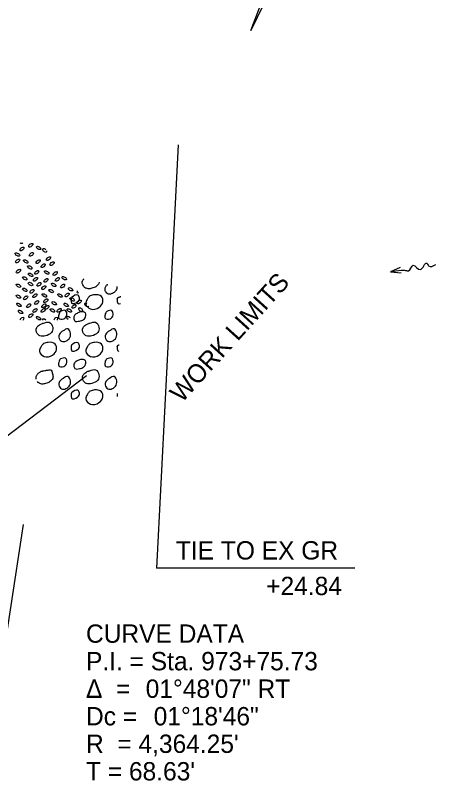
# Model space of a CAD drawing. Extents: x 1785 to 2465, y -264 to 295.
# Drawn here: x 2238.8 to 2303, y -70.4 to 46.4 of the extents above; entities that cross this region are included whole.
import ezdxf

# ---------------------------------------------------------------- set-up
doc = ezdxf.new("R2010")
doc.units = 0
for name, color, linetype in [('DR_P_Culvert', 7, 'Continuous'), ('DR_X_Erosion_Control', 7, 'Continuous'), ('MT_P_Lane_Line', 7, 'Continuous'), ('PV_P_Shoulder', 7, 'Continuous'), ('RW_X_CL_100_Curve_Data', 7, 'Continuous'), ('TX_P_1', 7, 'Continuous')]:
    doc.layers.add(name, color=color, linetype=linetype)

msp = doc.modelspace()

# ---------------------------------------------------------------- linework, layer by layer
at = {"layer": 'DR_P_Culvert'}
msp.add_line((2235.1, -63.51), (2240.05, -31.26), dxfattribs=at)
at = {"layer": 'DR_X_Erosion_Control'}
for centre, major_axis, start_param, end_param in [((2239.61, 11.87), (0.33, -0.195), 4.705104, 6.283185), ((2239.61, 11.87), (0.33, -0.195), 0, 0.101744), ((2243.28, 10.54), (0.33, -0.195), 1.269797, 6.283185), ((2243.28, 10.54), (0.33, -0.195), 0, 0.516671), ((2248.52, 4.35), (0.296, 0.243), 2.064503, 4.182694), ((2249.71, 2.22), (0.33, -0.195), 1.720823, 6.283185), ((2248.76, 1.5), (0.33, -0.195), 0, 5.743204), ((2248.76, 1.5), (0.33, -0.195), 6.256482, 6.283185), ((2249.71, 2.22), (0.33, -0.195), 0, 0.065645), ((2239.81, 0.03), (0.296, 0.243), 0, 2.52413), ((2239.81, 0.03), (0.296, 0.243), 4.857893, 6.283185), ((2243.28, -0.19), (0.33, -0.195), 1.299888, 3.572242), ((2244.98, 0.03), (0.296, 0.243), 0, 2.52413), ((2244.98, 0.03), (0.296, 0.243), 4.857893, 6.283185), ((2246.95, 0.2), (0.33, -0.195), 1.011335, 4.705166)]:
    msp.add_ellipse(centre, major_axis=major_axis, ratio=0.503326, start_param=start_param, end_param=end_param, dxfattribs=at)
for centre, major_axis in [((2239.81, 10.76), (0.296, 0.243)), ((2241.16, 11.33), (0.296, 0.243)), ((2242.36, 10.91), (0.33, -0.195)), ((2239.12, 9.91), (0.33, -0.195)), ((2241.24, 9.92), (0.296, 0.243)), ((2243.87, 9.29), (0.296, 0.243)), ((2239.16, 8.94), (0.296, 0.243)), ((2240.4, 8.85), (0.33, -0.195)), ((2241, 7.94), (0.33, -0.195)), ((2242.29, 8.83), (0.296, 0.243)), ((2243.05, 8.2), (0.296, 0.243)), ((2244.41, 8.52), (0.296, 0.243)), ((2239.27, 7.37), (0.296, 0.243)), ((2241.12, 6.82), (0.33, -0.195)), ((2242.06, 7.18), (0.296, 0.243)), ((2243.6, 7.16), (0.33, -0.195)), ((2244.89, 7.01), (0.296, 0.243)), ((2240.25, 6.27), (0.33, -0.195)), ((2241.88, 6.14), (0.296, 0.243)), ((2243.49, 5.97), (0.296, 0.243)), ((2245.22, 6.1), (0.296, 0.243)), ((2246.26, 6.3), (0.33, -0.195)), ((2239.28, 5.15), (0.33, -0.195)), ((2240.25, 4.53), (0.33, -0.195)), ((2241.12, 5.41), (0.33, -0.195)), ((2242.41, 5.35), (0.296, 0.243)), ((2243.15, 4.86), (0.296, 0.243)), ((2244.67, 5.27), (0.33, -0.195)), ((2246.02, 5.1), (0.296, 0.243)), ((2247.24, 4.6), (0.33, -0.195)), ((2239.28, 3.48), (0.33, -0.195)), ((2240.37, 3.3), (0.296, 0.243)), ((2241.35, 4.31), (0.296, 0.243)), ((2241.79, 3.63), (0.296, 0.243)), ((2243.23, 3.66), (0.33, -0.195)), ((2244.26, 4.34), (0.33, -0.195)), ((2245.64, 3.65), (0.33, -0.195)), ((2246.71, 3.74), (0.296, 0.243)), ((2239.36, 2.22), (0.33, -0.195)), ((2240.83, 2.09), (0.296, 0.243)), ((2242.06, 2.59), (0.296, 0.243)), ((2243.16, 2.09), (0.296, 0.243)), ((2243.45, 2.85), (0.296, 0.243)), ((2244.75, 2.47), (0.33, -0.195)), ((2246.57, 2.22), (0.33, -0.195)), ((2247.47, 3.06), (0.33, -0.195)), ((2248.55, 2.68), (0.296, 0.243)), ((2239.61, 1.15), (0.33, -0.195)), ((2241.8, 1.37), (0.296, 0.243)), ((2243.05, 1.38), (0.296, 0.243)), ((2243.64, 1.86), (0.296, 0.243)), ((2244.46, 1.38), (0.33, -0.195)), ((2245.48, 1.38), (0.296, 0.243)), ((2247.03, 1.38), (0.33, -0.195)), ((2247.76, 1.99), (0.296, 0.243)), ((2241.16, 0.6), (0.296, 0.243)), ((2242.36, 0.19), (0.33, -0.195))]:
    msp.add_ellipse(centre, major_axis=major_axis, ratio=0.503326, dxfattribs=at)
at = {"layer": 'MT_P_Lane_Line'}
for p, q in [((2297.57, 7.94), (2296.06, 7.26)), ((2296.06, 7.26), (2297.71, 7.09))]:
    msp.add_line(p, q, dxfattribs=at)
msp.add_spline([(2296.06, 7.26), (2297.7, 7.52), (2298.38, 7.48), (2298.81, 7.4), (2299.53, 8.26), (2300.62, 7.6), (2301.6, 8.59), (2301.89, 8.19), (2302.97, 8.37)], degree=3, dxfattribs=at)
at = {"layer": 'PV_P_Shoulder'}
for points, degree in [([(2251.59, 5.67), (2251.56, 5.53), (2251.49, 5.38), (2251.38, 5.26), (2251.11, 4.97), (2250.82, 4.85), (2250.49, 4.76), (2250.21, 4.67), (2249.89, 4.64), (2249.61, 4.76), (2249.44, 4.83), (2249.31, 4.96), (2249.21, 5.12), (2249.04, 5.39), (2248.99, 5.76), (2249.14, 6.01), (2249.18, 6.08), (2249.23, 6.15), (2249.29, 6.22)], 3), ([(2254.31, 5.02), (2254.33, 4.79), (2254.25, 4.55), (2254.07, 4.33), (2253.87, 4.09), (2253.65, 3.98), (2253.41, 3.91), (2253.21, 3.85), (2252.97, 3.84), (2252.79, 4.03), (2252.56, 4.25), (2252.47, 4.52), (2252.52, 4.75), (2252.55, 4.93), (2252.64, 5.17), (2252.81, 5.28), (2252.85, 5.3), (2252.88, 5.33), (2252.92, 5.35)], 3), ([(2254.46, 3.33), (2254.6, 3.39), (2254.75, 3.45), (2254.89, 3.5)], 2), ([(2254.85, 2.37), (2254.68, 2.33), (2254.52, 2.36), (2254.47, 2.5), (2254.4, 2.66), (2254.39, 2.82), (2254.39, 2.98), (2254.38, 3.06), (2254.35, 3.15), (2254.4, 3.23), (2254.42, 3.26), (2254.44, 3.29), (2254.46, 3.33)], 3), ([(2254.62, -4.89), (2254.55, -4.87), (2254.49, -4.83), (2254.47, -4.76), (2254.4, -4.6), (2254.39, -4.44), (2254.39, -4.28), (2254.38, -4.2), (2254.35, -4.11), (2254.4, -4.04), (2254.42, -4), (2254.44, -3.97), (2254.46, -3.93)], 3), ([(2254.46, -3.93), (2254.52, -3.91), (2254.59, -3.88), (2254.65, -3.85)], 2), ([(2242, -9.09), (2241.95, -8.89), (2241.97, -8.68), (2242.07, -8.51), (2242.17, -8.35), (2242.3, -8.2), (2242.48, -8.09), (2242.62, -7.99), (2242.76, -7.9), (2242.93, -7.87), (2242.98, -7.86), (2243.04, -7.85), (2243.09, -7.83)], 3), ([(2243.08, -7.84), (2243.38, -7.79), (2243.68, -7.73), (2243.98, -7.69), (2244.29, -7.64), (2244.43, -8.16), (2244.5, -8.45), (2244.57, -8.7), (2244.53, -9.02), (2244.31, -9.26), (2244.04, -9.55), (2243.75, -9.67), (2243.42, -9.76), (2243.13, -9.85), (2242.82, -9.88), (2242.54, -9.76), (2242.39, -9.7), (2242.28, -9.6), (2242.19, -9.47)], 3), ([(2254.4, -11.73), (2254.39, -11.66), (2254.39, -11.6), (2254.39, -11.54), (2254.38, -11.46), (2254.35, -11.37), (2254.4, -11.3), (2254.4, -11.29), (2254.41, -11.28), (2254.41, -11.27)], 3)]:
    msp.add_open_spline(points, degree=degree, dxfattribs=at)
for points in [[(2247.39, 3.33), (2248.34, 3.71), (2248.59, 3.28), (2248.29, 2.67), (2247.39, 2.5), (2247.32, 2.98), (2247.32, 3.23), (2247.39, 3.33)], [(2250.19, 3.58), (2250.9, 3.77), (2251.94, 3.5), (2252.16, 2.7), (2251.57, 1.83), (2250.27, 1.61), (2249.56, 2.4), (2249.75, 3.04), (2250.03, 3.43), (2250.19, 3.58)], [(2245.7, 1.23), (2246.46, 1.35), (2246.67, 0.69), (2246.19, 0.1), (2245.42, 0.21), (2245.42, 0.71), (2245.54, 1.03), (2245.7, 1.23)], [(2247.97, 0.8), (2248.47, 1.05), (2249.08, 1.17), (2249.5, 1), (2249.57, 0.6), (2249.22, 0), (2248.6, -0.24), (2247.89, -0.22), (2247.72, 0.21), (2247.83, 0.61), (2247.97, 0.8)], [(2252.77, 1.23), (2253.53, 1.35), (2253.74, 0.69), (2253.26, 0.1), (2252.49, 0.21), (2252.49, 0.71), (2252.61, 1.03), (2252.77, 1.23)], [(2243.08, -0.58), (2243.98, -0.43), (2244.5, -1.19), (2244.31, -2), (2243.42, -2.5), (2242.54, -2.5), (2242.14, -2.14), (2242.07, -1.25), (2242.48, -0.83), (2242.93, -0.61), (2243.09, -0.57)], [(2250.15, -0.58), (2251.06, -0.43), (2251.57, -1.19), (2251.38, -2), (2250.49, -2.5), (2249.61, -2.5), (2249.21, -2.14), (2249.14, -1.25), (2249.55, -0.83), (2250, -0.61), (2250.16, -0.57)], [(2246.11, -1.74), (2246.81, -1.44), (2247.23, -2.12), (2247, -2.93), (2246.34, -3.35), (2245.71, -3.23), (2245.45, -2.52), (2245.74, -1.98), (2246.11, -1.74)], [(2253.18, -1.74), (2253.88, -1.44), (2254.3, -2.12), (2254.07, -2.93), (2253.41, -3.35), (2252.79, -3.23), (2252.52, -2.52), (2252.81, -1.98), (2253.18, -1.74)], [(2243.12, -3.68), (2243.83, -3.49), (2244.87, -3.76), (2245.09, -4.56), (2244.49, -5.43), (2243.2, -5.65), (2242.49, -4.86), (2242.68, -4.22), (2242.96, -3.84), (2243.12, -3.68)], [(2247.39, -3.93), (2248.34, -3.55), (2248.59, -3.98), (2248.29, -4.59), (2247.39, -4.76), (2247.32, -4.28), (2247.32, -4.04), (2247.39, -3.93)], [(2250.19, -3.68), (2250.9, -3.49), (2251.94, -3.76), (2252.16, -4.56), (2251.57, -5.43), (2250.27, -5.65), (2249.56, -4.86), (2249.75, -4.22), (2250.03, -3.84), (2250.19, -3.68)], [(2245.7, -6.03), (2246.46, -5.91), (2246.67, -6.57), (2246.19, -7.16), (2245.42, -7.05), (2245.42, -6.55), (2245.54, -6.23), (2245.7, -6.03)], [(2252.77, -6.03), (2253.53, -5.91), (2253.74, -6.57), (2253.26, -7.16), (2252.49, -7.05), (2252.49, -6.55), (2252.61, -6.23), (2252.77, -6.03)], [(2247.97, -6.46), (2248.47, -6.21), (2249.08, -6.09), (2249.5, -6.26), (2249.57, -6.66), (2249.22, -7.26), (2248.6, -7.5), (2247.89, -7.48), (2247.72, -7.05), (2247.83, -6.65), (2247.97, -6.46)], [(2250.15, -7.84), (2251.06, -7.69), (2251.57, -8.45), (2251.38, -9.26), (2250.49, -9.76), (2249.61, -9.76), (2249.21, -9.4), (2249.14, -8.51), (2249.55, -8.09), (2250, -7.87), (2250.16, -7.83)], [(2246.11, -9), (2246.81, -8.7), (2247.23, -9.38), (2247, -10.19), (2246.34, -10.61), (2245.71, -10.49), (2245.45, -9.78), (2245.74, -9.24), (2246.11, -9)], [(2253.18, -9), (2253.88, -8.7), (2254.3, -9.38), (2254.07, -10.19), (2253.41, -10.61), (2252.79, -10.49), (2252.52, -9.78), (2252.81, -9.24), (2253.18, -9)], [(2247.39, -11.19), (2248.34, -10.81), (2248.59, -11.24), (2248.29, -11.85), (2247.39, -12.02), (2247.32, -11.54), (2247.32, -11.3), (2247.39, -11.19)], [(2250.19, -10.94), (2250.9, -10.75), (2251.94, -11.02), (2252.16, -11.82), (2251.57, -12.69), (2250.27, -12.91), (2249.56, -12.12), (2249.75, -11.48), (2250.03, -11.1), (2250.19, -10.94)]]:
    msp.add_spline(points, degree=3, dxfattribs=at)
at = {"layer": 'TX_P_1'}
for p, q in [((2263.66, 26.65), (2260.35, -37.92)), ((2220.74, -30.53), (2249.66, -8.53)), ((2290.63, -37.92), (2260.35, -37.92))]:
    msp.add_line(p, q, dxfattribs=at)
msp.add_lwpolyline([(2296.31, 88.37), (2274.73, 44.09), (2291.63, 88.37)], dxfattribs=at)

# ---------------------------------------------------------------- texts
at = {"layer": 'RW_X_CL_100_Curve_Data'}
for s, p in [('CURVE DATA', (2249.59, -49.32)), ('P.I. = Sta. 973+75.73', (2249.59, -53.52)), ('Δ  = ', (2249.59, -57.72)), ('01°48\'07" RT', (2258.7, -57.72)), ('Dc = ', (2249.59, -61.92)), ('01°18\'46"', (2259.92, -61.92)), ("R  = 4,364.25'", (2249.59, -66.12)), ("T = 68.63'", (2249.59, -70.32))]:
    msp.add_text(s, height=2.8, dxfattribs=at).set_placement(p)
at = {"layer": 'TX_P_1'}
msp.add_text('WORK LIMITS', height=2.8, rotation=47.8927, dxfattribs=at).set_placement((2264.22, -12.84))
for s, p in [('TIE TO EX GR', (2263.31, -36.62)), ('+24.84', (2277.1, -42.05))]:
    msp.add_text(s, height=2.8, dxfattribs=at).set_placement(p)

doc.saveas('drawing.dxf')
